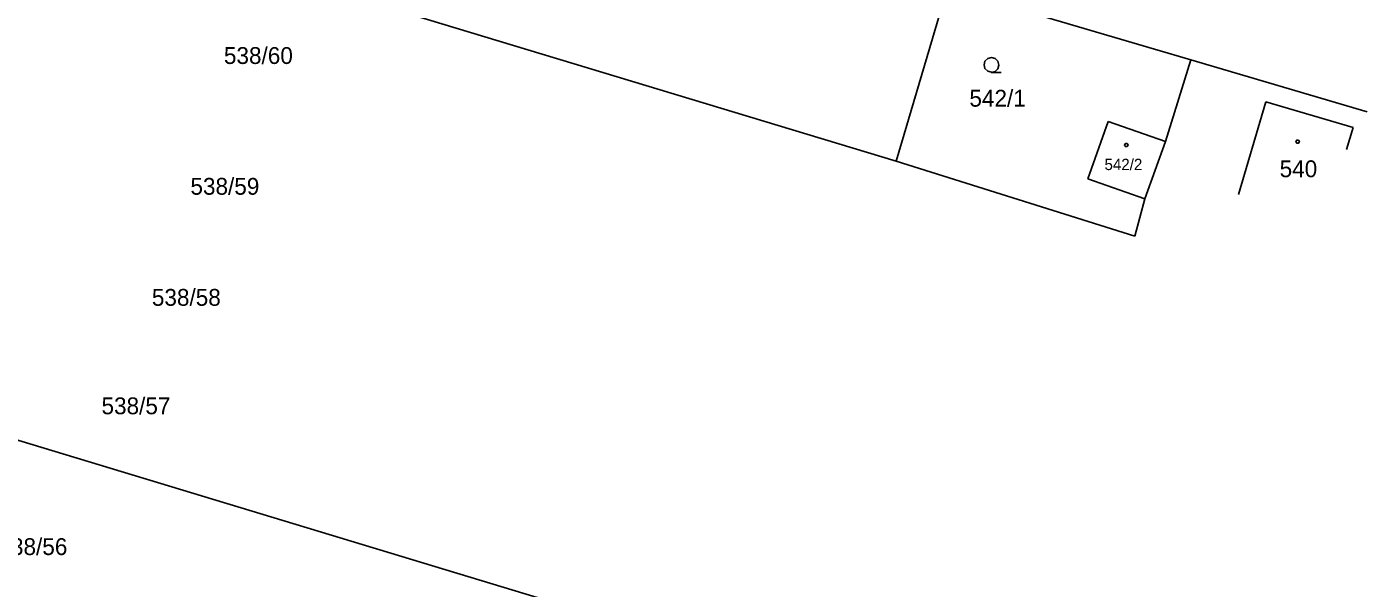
# Model space of a CAD drawing. Extents: x -759060 to -757386, y -1172273 to -1170948.
# Drawn here: x -758324 to -758188.7, y -1171791.3 to -1171734.6 of the extents above; entities that cross this region are included whole.
import ezdxf

# ---------------------------------------------------------------- set-up
doc = ezdxf.new("R2010")
doc.units = 0
for name, color, linetype in [('Vrstva 1', 7, 'Continuous'), ('Vrstva 12', 7, 'Continuous'), ('Vrstva 2', 7, 'Continuous'), ('Vrstva 3', 7, 'Continuous'), ('Vrstva 4', 7, 'Continuous'), ('Vrstva 5', 7, 'Continuous')]:
    doc.layers.add(name, color=color, linetype=linetype)

msp = doc.modelspace()

# ---------------------------------------------------------------- linework, layer by layer
at = {"layer": 'Vrstva 1'}
for p, q in [((-758333.99, -1171718.6), (-758236.26, -1171748.17)), ((-758231.11, -1171730.71), (-758236.26, -1171748.17)), ((-758222.66, -1171733.2), (-758206.53, -1171737.95)), ((-758206.53, -1171737.95), (-758209.1, -1171746.18)), ((-758206.53, -1171737.95), (-758188.74, -1171743.19)), ((-758188.74, -1171743.19), (-758188.74, -1171743.19)), ((-758188.74, -1171743.19), (-758188.74, -1171743.19)), ((-758216.92, -1171749.96), (-758214.86, -1171744.19)), ((-758214.86, -1171744.19), (-758209.1, -1171746.18)), ((-758209.1, -1171746.18), (-758211.16, -1171752)), ((-758190.83, -1171746.99), (-758190.83, -1171746.99)), ((-758190.83, -1171746.99), (-758190.83, -1171746.99)), ((-758414.42, -1171749.29), (-758250.49, -1171798.86)), ((-758236.26, -1171748.17), (-758212.17, -1171755.74)), ((-758211.16, -1171752), (-758216.92, -1171749.96)), ((-758211.16, -1171752), (-758212.17, -1171755.74)), ((-758212.17, -1171755.74), (-758212.17, -1171755.74))]:
    msp.add_line(p, q, dxfattribs=at)
at = {"layer": 'Vrstva 12'}
for p, q in [((-758198.95, -1171742.2), (-758201.72, -1171751.56)), ((-758190.16, -1171744.8), (-758198.95, -1171742.2)), ((-758216.92, -1171749.96), (-758214.86, -1171744.19)), ((-758214.86, -1171744.19), (-758209.1, -1171746.18)), ((-758190.16, -1171744.8), (-758190.83, -1171746.99)), ((-758209.1, -1171746.18), (-758211.16, -1171752)), ((-758190.83, -1171746.99), (-758190.83, -1171746.99)), ((-758211.16, -1171752), (-758216.92, -1171749.96)), ((-758201.72, -1171751.56), (-758201.72, -1171751.56))]:
    msp.add_line(p, q, dxfattribs=at)
at = {"layer": 'Vrstva 3'}
msp.add_lwpolyline([(-758226.65, -1171739.21), (-758227.03, -1171739.11), (-758227.3, -1171738.84), (-758227.4, -1171738.47), (-758227.3, -1171738.1), (-758227.03, -1171737.83), (-758226.66, -1171737.73), (-758226.29, -1171737.83), (-758226.02, -1171738.1), (-758225.92, -1171738.48), (-758226.02, -1171738.86), (-758226.29, -1171739.13), (-758226.67, -1171739.23), (-758225.67, -1171739.23)], dxfattribs=at)
at = {"layer": 'Vrstva 4'}
for p, q in [((-758198.95, -1171742.2), (-758201.72, -1171751.56)), ((-758190.16, -1171744.8), (-758198.95, -1171742.2)), ((-758190.16, -1171744.8), (-758190.83, -1171746.99)), ((-758201.72, -1171751.56), (-758201.72, -1171751.56))]:
    msp.add_line(p, q, dxfattribs=at)
at = {"layer": 'Vrstva 5'}
for points in [[(-758212.96, -1171746.41), (-758212.87, -1171746.56), (-758212.96, -1171746.71), (-758213.14, -1171746.71), (-758213.23, -1171746.56), (-758213.14, -1171746.41)], [(-758195.66, -1171746.06), (-758195.57, -1171746.21), (-758195.66, -1171746.36), (-758195.84, -1171746.36), (-758195.93, -1171746.21), (-758195.84, -1171746.06)]]:
    msp.add_lwpolyline(points, close=True, dxfattribs=at)

# ---------------------------------------------------------------- texts
at = {"layer": 'Vrstva 2'}
for s, height, p in [('538/60', 1.7, (-758304.083, -1171738.37)), ('542/1', 1.7, (-758228.873, -1171742.68)), ('542/2', 1.14, (-758215.241, -1171749.08)), ('540', 1.7, (-758197.573, -1171749.8)), ('538/59', 1.7, (-758307.463, -1171751.57)), ('538/58', 1.7, (-758311.353, -1171762.78)), ('538/57', 1.7, (-758316.433, -1171773.73)), ('538/56', 1.7, (-758326.833, -1171787.94))]:
    msp.add_text(s, height=height, dxfattribs=at).set_placement(p)

doc.saveas('drawing.dxf')
